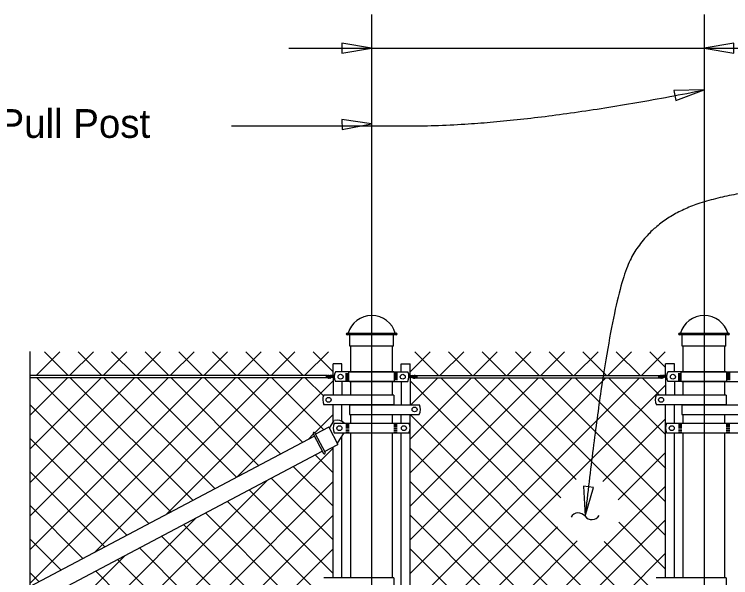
# Model space of a CAD drawing. Extents: x 0.5 to 39.7, y 0.9 to 25.6.
# Drawn here: x 23.73 to 28.76, y 21.55 to 25.5 of the extents above; entities that cross this region are included whole.
import ezdxf

# ---------------------------------------------------------------- set-up
doc = ezdxf.new("R2010")
doc.units = 0
for name, color, linetype in [('CL_Major', 7, 'Continuous'), ('Dimension', 7, 'Continuous'), ('Miscellaneous', 7, 'Continuous'), ('SteelMisc', 7, 'Continuous'), ('TextStructures', 7, 'Continuous')]:
    doc.layers.add(name, color=color, linetype=linetype)

msp = doc.modelspace()

# ---------------------------------------------------------------- linework, layer by layer
at = {"layer": 'CL_Major'}
for p, q in [((26.2429, 25.5043), (26.2429, 12.3953)), ((28.5763, 25.5043), (28.5763, 13.5039))]:
    msp.add_line(p, q, dxfattribs=at)
at = {"layer": 'Dimension'}
msp.add_line((25.6609, 25.2672), (34.1233, 25.2672), dxfattribs=at)
for points in [[(26.2429, 25.2672), (26.0347, 25.3025), (26.0347, 25.2319)], [(28.5762, 25.2672), (28.7845, 25.2319), (28.7845, 25.3025)], [(28.5762, 24.9738), (28.3651, 24.9702), (28.378, 24.9009)], [(26.2429, 24.737), (26.0337, 24.766), (26.0358, 24.6954)], [(27.7412, 21.9834), (27.8008, 22.186), (27.7307, 22.1943)]]:
    msp.add_lwpolyline(points, close=True, dxfattribs=at)
msp.add_lwpolyline([(23.8431, 23.1382), (23.8431, 21.1819), (23.9465, 21.1819), (23.8431, 21.1369), (23.7398, 21.0919), (23.8431, 21.0919), (23.8431, 20.1983)], dxfattribs=at)
for centre, start, end in [((27.6938, 21.9472), 37.4003, 149.1275), ((27.7886, 22.0196), 217.4003, 329.1275)]:
    msp.add_arc(centre, 0.0596, start, end, dxfattribs=at)
for points in [[(25.2588, 24.7214), (25.7125, 24.7214), (27.3088, 24.7214), (28.5763, 24.9737)], [(29.3712, 24.2725), (28.9427, 24.2977), (28.2117, 24.0791), (27.9092, 23.4903), (27.7412, 21.9834)]]:
    msp.add_open_spline(points, degree=2, dxfattribs=at)
at = {"layer": 'Miscellaneous'}
for p, q in [((24.0538, 23.1361), (23.8871, 22.9695)), ((24.113, 22.9695), (23.9463, 23.1361)), ((24.2895, 23.1361), (24.1228, 22.9695)), ((24.3487, 22.9695), (24.182, 23.1361)), ((24.5252, 23.1361), (24.3585, 22.9695)), ((24.5844, 22.9695), (24.4177, 23.1361)), ((24.7609, 23.1361), (24.5942, 22.9695)), ((24.8201, 22.9695), (24.6534, 23.1361)), ((24.9966, 23.1361), (24.8299, 22.9695)), ((25.0558, 22.9695), (24.8891, 23.1361)), ((25.2323, 23.1361), (25.0656, 22.9695)), ((25.2915, 22.9695), (25.1248, 23.1361)), ((25.468, 23.1361), (25.3013, 22.9695)), ((25.5272, 22.9695), (25.3605, 23.1361)), ((25.7037, 23.1361), (25.537, 22.9695)), ((25.7629, 22.9695), (25.5962, 23.1361)), ((25.9394, 23.1361), (25.7727, 22.9695)), ((25.972, 22.996), (25.8319, 23.1361)), ((26.5138, 22.996), (26.6539, 23.1361)), ((26.5465, 23.1361), (26.7131, 22.9695)), ((26.7229, 22.9695), (26.8896, 23.1361)), ((26.7822, 23.1361), (26.9488, 22.9695)), ((26.9586, 22.9695), (27.1253, 23.1361)), ((27.0179, 23.1361), (27.1845, 22.9695)), ((27.1943, 22.9695), (27.361, 23.1361)), ((27.2536, 23.1361), (27.4202, 22.9695)), ((27.4301, 22.9695), (27.5967, 23.1361)), ((27.4893, 23.1361), (27.6559, 22.9695)), ((27.6658, 22.9695), (27.8324, 23.1361)), ((27.725, 23.1361), (27.8916, 22.9695)), ((27.9015, 22.9695), (28.0681, 23.1361)), ((27.9607, 23.1361), (28.1273, 22.9695)), ((28.1372, 22.9695), (28.3038, 23.1361)), ((28.1964, 23.1361), (28.3054, 23.0271)), ((25.2865, 22.9547), (23.8431, 21.5113)), ((25.0508, 22.9547), (23.8431, 21.747)), ((24.8151, 22.9547), (23.8431, 21.9827)), ((24.5794, 22.9547), (23.8431, 22.2184)), ((24.3437, 22.9547), (23.8431, 22.4541)), ((24.108, 22.9547), (23.8431, 22.6898)), ((24.8328, 22.014), (23.892, 22.9547)), ((24.987, 22.0955), (24.1277, 22.9547)), ((25.5223, 22.9547), (24.3, 21.7324)), ((25.1412, 22.177), (24.3634, 22.9547)), ((25.2954, 22.2584), (24.5991, 22.9547)), ((25.758, 22.9547), (24.7998, 21.9966)), ((25.4496, 22.3399), (24.8348, 22.9547)), ((25.6038, 22.4214), (25.0705, 22.9547)), ((25.972, 22.9331), (25.2997, 22.2607)), ((25.758, 22.5029), (25.3062, 22.9547)), ((25.9072, 22.5894), (25.5419, 22.9547)), ((25.905, 22.8273), (25.7776, 22.9547)), ((26.5138, 22.2889), (27.1796, 22.9547)), ((26.5138, 21.5818), (27.8867, 22.9547)), ((26.5138, 21.8175), (27.651, 22.9547)), ((26.5138, 22.0532), (27.4153, 22.9547)), ((26.5138, 21.3461), (28.1224, 22.9547)), ((26.5138, 22.5246), (26.9439, 22.9547)), ((26.5138, 22.9331), (28.3054, 21.1415)), ((26.5188, 22.7654), (26.7082, 22.9547)), ((26.7279, 22.9547), (27.5705, 22.1121)), ((26.9636, 22.9547), (27.6781, 22.2402)), ((27.1993, 22.9547), (28.3054, 21.8486)), ((27.435, 22.9547), (28.3054, 22.0843)), ((27.6707, 22.9547), (28.308, 22.3174)), ((27.9064, 22.9547), (28.3054, 22.5557)), ((28.1421, 22.9547), (28.2638, 22.833)), ((26.5138, 21.1104), (28.3054, 22.902)), ((24.6785, 21.9325), (23.8447, 22.7664)), ((25.972, 22.6974), (25.8432, 22.5686)), ((26.5138, 22.6974), (28.3054, 20.9058)), ((27.8667, 22.2276), (28.3054, 22.6663)), ((24.5243, 21.851), (23.8431, 22.5322)), ((25.8333, 22.5587), (25.7995, 22.5249)), ((25.972, 22.4617), (23.8431, 20.3328)), ((26.5138, 22.4617), (28.3054, 20.6701)), ((27.9743, 22.0995), (28.3054, 22.4306)), ((25.972, 22.2889), (25.8468, 22.4142)), ((25.972, 22.0532), (25.6926, 22.3327)), ((24.3701, 21.7695), (23.8431, 22.2965)), ((25.5118, 22.2371), (23.8431, 20.5685)), ((25.972, 21.8175), (25.5384, 22.2512)), ((25.972, 22.226), (23.8431, 20.0971)), ((26.5138, 22.226), (28.3054, 20.4344)), ((26.5138, 20.4033), (28.3054, 22.1949)), ((25.972, 21.5818), (25.3841, 22.1697)), ((25.972, 21.3461), (25.2299, 22.0882)), ((24.2159, 21.688), (23.8431, 22.0608)), ((25.972, 21.9903), (23.8431, 19.8614)), ((25.9649, 21.1175), (25.0757, 22.0067)), ((26.5138, 21.9903), (28.2366, 20.2675)), ((25.012, 21.973), (23.8431, 20.8042)), ((25.972, 20.8747), (24.9215, 21.9252)), ((26.5505, 20.2043), (28.3054, 21.9592)), ((27.9776, 21.9407), (28.3054, 21.6129)), ((26.5138, 20.8747), (27.5488, 21.9097)), ((24.0617, 21.6065), (23.8431, 21.8251)), ((25.972, 20.639), (24.7673, 21.8437)), ((26.5138, 20.639), (27.685, 21.8102)), ((27.8761, 21.8065), (28.3054, 21.3772)), ((25.972, 21.7546), (23.8431, 19.6257)), ((25.972, 20.4033), (24.6131, 21.7622)), ((26.5138, 21.7546), (28.3054, 19.963)), ((26.5138, 19.9319), (28.3054, 21.7235)), ((24.5121, 21.7089), (23.8431, 21.0399)), ((25.8996, 20.24), (24.4589, 21.6807)), ((23.9075, 21.525), (23.8431, 21.5894)), ((25.972, 19.9319), (24.3047, 21.5992))]:
    msp.add_line(p, q, dxfattribs=at)
at = {"layer": 'SteelMisc'}
for p, q in [((26.0707, 23.2681), (26.4153, 23.2681)), ((26.4153, 23.2559), (26.0707, 23.2559)), ((26.0889, 23.1761), (26.0889, 23.2559)), ((26.397, 23.1761), (26.397, 23.2559)), ((28.404, 23.2681), (28.7486, 23.2681)), ((28.7486, 23.2559), (28.404, 23.2559)), ((28.4222, 23.1761), (28.4222, 23.2559)), ((28.7304, 23.1761), (28.7304, 23.2559)), ((26.397, 23.1761), (26.0889, 23.1761)), ((26.0971, 22.9966), (26.0971, 23.1761)), ((26.3888, 22.9966), (26.3888, 23.1761)), ((28.7304, 23.1761), (28.4222, 23.1761)), ((28.4305, 22.9966), (28.4305, 23.1761)), ((28.7221, 22.9966), (28.7221, 23.1761)), ((25.972, 22.9726), (25.972, 23.0528)), ((26.0345, 23.0528), (25.972, 23.0528)), ((26.0345, 22.9966), (26.0345, 23.0528)), ((26.4513, 22.9966), (26.4513, 23.0528)), ((26.4513, 23.0528), (26.5138, 23.0528)), ((26.4513, 22.9966), (26.4513, 23.0528)), ((26.4513, 23.0528), (26.5138, 23.0528)), ((26.5138, 22.9726), (26.5138, 23.0528)), ((26.5138, 22.9726), (26.5138, 23.0528)), ((28.3054, 22.9726), (28.3054, 23.0528)), ((28.3679, 23.0528), (28.3054, 23.0528)), ((28.3679, 22.9966), (28.3679, 23.0528)), ((26.3988, 22.9966), (25.989, 22.9966)), ((26.0604, 22.9858), (26.0834, 22.9858)), ((26.0834, 22.9289), (26.0834, 22.9966)), ((26.0872, 22.9966), (26.4969, 22.9966)), ((26.4254, 22.9858), (26.4024, 22.9858)), ((26.4026, 22.9289), (26.4026, 22.9966)), ((28.7321, 22.9966), (28.3223, 22.9966)), ((28.3937, 22.9858), (28.4167, 22.9858)), ((28.4167, 22.9289), (28.4167, 22.9966)), ((28.4206, 22.9966), (28.8303, 22.9966)), ((28.7588, 22.9858), (28.7358, 22.9858)), ((28.7359, 22.9289), (28.7359, 22.9966)), ((25.9337, 22.9695), (23.8431, 22.9695)), ((25.935, 22.9547), (23.8431, 22.9547)), ((25.9811, 22.9537), (25.9474, 22.9593)), ((25.9807, 22.9585), (25.9509, 22.9634)), ((25.9817, 22.9741), (25.9524, 22.9695)), ((25.981, 22.9691), (25.9549, 22.965)), ((25.972, 22.9676), (25.972, 22.9598)), ((25.972, 22.9552), (25.972, 22.833)), ((26.0604, 22.9802), (26.0834, 22.9802)), ((26.0604, 22.9722), (26.0834, 22.9722)), ((26.0604, 22.9667), (26.0834, 22.9667)), ((26.0604, 22.9587), (26.0834, 22.9587)), ((26.0604, 22.9531), (26.0834, 22.9531)), ((26.0604, 22.9451), (26.0834, 22.9451)), ((26.0604, 22.9396), (26.0834, 22.9396)), ((26.4254, 22.9802), (26.4024, 22.9802)), ((26.4254, 22.9722), (26.4024, 22.9722)), ((26.4254, 22.9667), (26.4024, 22.9667)), ((26.4254, 22.9587), (26.4024, 22.9587)), ((26.4254, 22.9531), (26.4024, 22.9531)), ((26.4254, 22.9451), (26.4024, 22.9451)), ((26.4254, 22.9396), (26.4024, 22.9396)), ((26.5042, 22.9741), (26.5335, 22.9695)), ((26.5043, 22.9741), (26.5336, 22.9695)), ((26.5047, 22.9537), (26.5384, 22.9593)), ((26.5048, 22.9691), (26.5309, 22.965)), ((26.5048, 22.9537), (26.5385, 22.9593)), ((26.5049, 22.9691), (26.531, 22.965)), ((26.5052, 22.9585), (26.5351, 22.9634)), ((26.5053, 22.9585), (26.5352, 22.9634)), ((26.5138, 22.9676), (26.5138, 22.9598)), ((26.5138, 22.9676), (26.5138, 22.9598)), ((26.5138, 22.9552), (26.5138, 22.7653)), ((26.5138, 22.9552), (26.5138, 22.7653)), ((26.5509, 22.9547), (28.2683, 22.9547)), ((26.5522, 22.9695), (28.267, 22.9695)), ((28.3144, 22.9537), (28.2808, 22.9593)), ((28.314, 22.9585), (28.2842, 22.9634)), ((28.3151, 22.9741), (28.2858, 22.9695)), ((28.3143, 22.9691), (28.2883, 22.965)), ((28.3054, 22.9676), (28.3054, 22.9598)), ((28.3054, 22.9552), (28.3054, 22.833)), ((28.3937, 22.9802), (28.4167, 22.9802)), ((28.3937, 22.9722), (28.4167, 22.9722)), ((28.3937, 22.9667), (28.4167, 22.9667)), ((28.3937, 22.9587), (28.4167, 22.9587)), ((28.3937, 22.9531), (28.4167, 22.9531)), ((28.3937, 22.9451), (28.4167, 22.9451)), ((28.3937, 22.9396), (28.4167, 22.9396)), ((28.7588, 22.9802), (28.7358, 22.9802)), ((28.7588, 22.9722), (28.7358, 22.9722)), ((28.7588, 22.9667), (28.7358, 22.9667)), ((28.7588, 22.9587), (28.7358, 22.9587)), ((28.7588, 22.9531), (28.7358, 22.9531)), ((28.7588, 22.9451), (28.7358, 22.9451)), ((28.7588, 22.9396), (28.7358, 22.9396)), ((26.3988, 22.9289), (25.9894, 22.9289)), ((26.0345, 22.9288), (26.0345, 22.833)), ((26.0872, 22.9289), (26.4966, 22.9289)), ((26.0971, 22.833), (26.0971, 22.9288)), ((26.3888, 22.833), (26.3888, 22.9288)), ((26.4513, 22.9288), (26.4513, 22.7653)), ((26.4513, 22.9288), (26.4513, 22.7653)), ((28.7321, 22.9289), (28.3228, 22.9289)), ((28.3679, 22.9288), (28.3679, 22.833)), ((28.4206, 22.9289), (28.8299, 22.9289)), ((28.4305, 22.833), (28.4305, 22.9288)), ((28.7221, 22.833), (28.7221, 22.9288)), ((26.3988, 22.833), (25.9077, 22.833)), ((26.3988, 22.833), (26.3988, 22.7654)), ((28.7321, 22.833), (28.241, 22.833)), ((28.7321, 22.833), (28.7321, 22.7654)), ((26.3988, 22.7654), (25.9084, 22.7654)), ((25.972, 22.641), (25.972, 22.7654)), ((26.0345, 22.6487), (26.0345, 22.7654)), ((26.0872, 22.7654), (26.0872, 22.6977)), ((26.0872, 22.7654), (26.5783, 22.7654)), ((28.7321, 22.7654), (28.2417, 22.7654)), ((28.3054, 21.5524), (28.3054, 22.7654)), ((28.3679, 22.6358), (28.3679, 22.7654)), ((28.4206, 22.7654), (28.4206, 22.6977)), ((28.4206, 22.7654), (28.9116, 22.7654)), ((26.0872, 22.6977), (26.5776, 22.6977)), ((26.0971, 22.6358), (26.0971, 22.6977)), ((26.3888, 22.6358), (26.3888, 22.6977)), ((26.4513, 22.6358), (26.4513, 22.6977)), ((26.5138, 21.4848), (26.5138, 22.6977)), ((28.4206, 22.6977), (28.9109, 22.6977)), ((28.4305, 22.6358), (28.4305, 22.6977)), ((28.7221, 22.6358), (28.7221, 22.6977)), ((25.9464, 22.6018), (25.9811, 22.6549)), ((25.9806, 22.6358), (26.5054, 22.6358)), ((28.3139, 22.6358), (28.8387, 22.6358)), ((25.9429, 22.6083), (25.8486, 22.5585)), ((25.9429, 22.6083), (26.0066, 22.4877)), ((26.0629, 22.628), (26.0864, 22.628)), ((26.0629, 22.6184), (26.0864, 22.6184)), ((26.0629, 22.6075), (26.0864, 22.6075)), ((26.0629, 22.5958), (26.0864, 22.5958)), ((26.0629, 22.584), (26.0864, 22.584)), ((26.423, 22.628), (26.3995, 22.628)), ((26.423, 22.6184), (26.3995, 22.6184)), ((26.423, 22.6075), (26.3995, 22.6075)), ((26.423, 22.5958), (26.3995, 22.5958)), ((26.423, 22.584), (26.3995, 22.584)), ((28.3962, 22.628), (28.4197, 22.628)), ((28.3962, 22.6184), (28.4197, 22.6184)), ((28.3962, 22.6075), (28.4197, 22.6075)), ((28.3962, 22.5958), (28.4197, 22.5958)), ((28.3962, 22.584), (28.4197, 22.584)), ((28.7563, 22.628), (28.7328, 22.628)), ((28.7563, 22.6184), (28.7328, 22.6184)), ((28.7563, 22.6075), (28.7328, 22.6075)), ((28.7563, 22.5958), (28.7328, 22.5958)), ((28.7563, 22.584), (28.7328, 22.584)), ((23.8431, 21.491), (25.8399, 22.5462)), ((25.8321, 22.5609), (25.9046, 22.4237)), ((25.844, 22.5671), (25.9165, 22.43)), ((25.9806, 22.568), (26.5054, 22.568)), ((26.0024, 22.4958), (26.0493, 22.5675)), ((26.0345, 21.5524), (26.0345, 22.5449)), ((26.0629, 22.5742), (26.0864, 22.5742)), ((26.0971, 21.5524), (26.0971, 22.568)), ((26.3888, 21.5524), (26.3888, 22.568)), ((26.423, 22.5742), (26.3995, 22.5742)), ((26.4513, 21.4848), (26.4513, 22.568)), ((28.3139, 22.568), (28.8387, 22.568)), ((28.3679, 21.5524), (28.3679, 22.568)), ((28.3962, 22.5742), (28.4197, 22.5742)), ((28.4305, 21.5524), (28.4305, 22.568)), ((28.7221, 21.5524), (28.7221, 22.568)), ((28.7563, 22.5742), (28.7328, 22.5742)), ((25.9123, 22.4379), (26.0066, 22.4877)), ((23.8431, 21.3553), (25.8959, 22.4401)), ((25.972, 21.5524), (25.972, 22.4695)), ((26.3988, 21.5524), (25.9077, 21.5524)), ((26.3988, 21.5524), (26.3988, 21.4848)), ((28.7321, 21.5524), (28.241, 21.5524)), ((28.7321, 21.5524), (28.7321, 21.4848))]:
    msp.add_line(p, q, dxfattribs=at)
for centre, radius, start, end in [((26.0708, 23.2618), 0.00613, 91.1647, 268.8353), ((26.4151, 23.2618), 0.00613, 271.1647, 88.8353), ((28.4041, 23.2618), 0.00613, 91.1647, 268.8353), ((28.7484, 23.2618), 0.00613, 271.1647, 88.8353), ((25.8382, 22.5639), 0.00673, 27.851, 207.851), ((25.9107, 22.4267), 0.00673, 207.851, 27.851)]:
    msp.add_arc(centre, radius, start, end, dxfattribs=at)
for centre, major_axis, ratio, start_param, end_param in [((26.2436, 23.227), (0.1711, 0), 0.957868, 0.252602, 2.888574), ((28.5769, 23.227), (0.1711, 0), 0.957868, 0.252602, 2.888574), ((26.0582, 22.963), (-0.0776, 0), 0.957868, 5.81433, 6.762456), ((26.4276, 22.963), (0.0776, 0), 0.957868, 5.803915, 6.752041), ((26.4276, 22.963), (0.0776, 0), 0.957868, 5.803915, 6.752041), ((28.3916, 22.963), (-0.0776, 0), 0.957868, 5.81433, 6.762456), ((25.9448, 22.9412), (-0.0274, 0), 0.957868, 5.133531, 5.654664), ((25.9368, 22.9562), (0.0142, 0), 0.957868, 1.486836, 3.141593), ((25.942, 22.9608), (-0.00944, 0), 0.957868, 6.009018, 8.249874), ((25.9415, 22.9617), (0.00872, 0), 0.957868, 1.29026, 2.959852), ((25.9415, 22.9617), (0.00503, 0), 0.92697, 1.570796, 4.502291), ((25.9481, 22.9612), (0.00872, 0), 0.957868, 1.29026, 4.182385), ((25.9538, 22.9604), (-0.0115, -0.0041), 0.737732, 4.35367, 7.47816), ((25.9525, 22.9588), (-0.00527, 0), 0.957868, 5.22362, 7.507542), ((25.9504, 22.9579), (-0.00301, 0), 0.957868, 6.141288, 6.278592), ((25.9557, 22.9555), (-0.00982, 0), 0.957868, 4.777514, 5.62749), ((25.9504, 22.9579), (-0.00301, 0), 0.957868, 1.11255, 2.999696), ((25.9497, 22.9601), (0.00453, 0), 0.957868, 0.731188, 1.133458), ((25.9498, 22.9596), (0.0095, 0), 0.957868, 5.011765, 6.030719), ((25.9498, 22.9596), (0.0095, 0), 0.957868, 0.230606, 0.609214), ((26.536, 22.9596), (-0.0095, 0), 0.957868, 5.673972, 6.052579), ((26.536, 22.9596), (-0.0095, 0), 0.957868, 5.673972, 6.052579), ((26.536, 22.9596), (-0.0095, 0), 0.957868, 0.252467, 1.271421), ((26.536, 22.9596), (-0.0095, 0), 0.957868, 0.252467, 1.271421), ((26.5302, 22.9555), (0.00982, 0), 0.957868, 0.655696, 1.505671), ((26.5302, 22.9555), (0.00982, 0), 0.957868, 0.655696, 1.505671), ((26.5321, 22.9604), (0.0115, -0.0041), 0.737732, 5.08821, 8.212701), ((26.5321, 22.9604), (0.0115, -0.0041), 0.737732, 5.08821, 8.212701), ((26.5355, 22.9579), (0.00301, 0), 0.957868, 3.28349, 5.170635), ((26.5355, 22.9579), (0.00301, 0), 0.957868, 3.28349, 5.170635), ((26.5361, 22.9601), (-0.00453, 0), 0.957868, 5.149727, 5.551998), ((26.5361, 22.9601), (-0.00453, 0), 0.957868, 5.149727, 5.551998), ((26.5333, 22.9588), (0.00527, 0), 0.957868, 5.058829, 7.342751), ((26.5333, 22.9588), (0.00527, 0), 0.957868, 5.058829, 7.342751), ((26.5377, 22.9612), (-0.00872, 0), 0.957868, 2.1008, 4.992926), ((26.5377, 22.9612), (-0.00872, 0), 0.957868, 2.1008, 4.992926), ((26.5355, 22.9579), (0.00301, 0), 0.957868, 0.004594, 0.141897), ((26.5355, 22.9579), (0.00301, 0), 0.957868, 0.004594, 0.141897), ((26.5439, 22.9608), (0.00944, 0), 0.957868, 4.316497, 6.557353), ((26.5439, 22.9608), (0.00944, 0), 0.957868, 4.316497, 6.557353), ((26.5443, 22.9617), (-0.00872, 0), 0.957868, 3.323334, 4.992926), ((26.5443, 22.9617), (-0.00872, 0), 0.957868, 3.323334, 4.992926), ((26.5443, 22.9617), (-0.00503, 0), 0.92697, 1.780895, 4.712389), ((26.5443, 22.9617), (-0.00503, 0), 0.92697, 1.780895, 4.712389), ((26.549, 22.9562), (-0.0142, 0), 0.957868, 3.141593, 4.79635), ((26.549, 22.9562), (-0.0142, 0), 0.957868, 3.141593, 4.79635), ((26.541, 22.9412), (0.0274, 0), 0.957868, 0.628521, 1.149654), ((26.541, 22.9412), (0.0274, 0), 0.957868, 0.628521, 1.149654), ((28.2701, 22.9562), (0.0142, 0), 0.957868, 1.486836, 3.141593), ((28.2781, 22.9412), (-0.0274, 0), 0.957868, 5.133531, 5.654664), ((28.2753, 22.9608), (-0.00944, 0), 0.957868, 6.009018, 8.249874), ((28.2749, 22.9617), (0.00872, 0), 0.957868, 1.29026, 2.959852), ((28.2749, 22.9617), (0.00503, 0), 0.92697, 1.570796, 4.502291), ((28.2814, 22.9612), (0.00872, 0), 0.957868, 1.29026, 4.182385), ((28.2871, 22.9604), (-0.0115, -0.0041), 0.737732, 4.35367, 7.47816), ((28.2858, 22.9588), (-0.00527, 0), 0.957868, 5.22362, 7.507542), ((28.2837, 22.9579), (-0.00301, 0), 0.957868, 6.141288, 6.278592), ((28.289, 22.9555), (-0.00982, 0), 0.957868, 4.777514, 5.62749), ((28.2837, 22.9579), (-0.00301, 0), 0.957868, 1.11255, 2.999696), ((28.283, 22.9601), (0.00453, 0), 0.957868, 0.731188, 1.133458), ((28.2831, 22.9596), (0.0095, 0), 0.957868, 5.011765, 6.030719), ((28.2831, 22.9596), (0.0095, 0), 0.957868, 0.230606, 0.609214), ((25.9771, 22.7998), (-0.0776, 0), 0.957868, 5.821213, 6.765127), ((28.3105, 22.7998), (-0.0776, 0), 0.957868, 5.821213, 6.765127), ((26.5087, 22.7322), (0.0776, 0), 0.957868, 5.801244, 6.745158), ((26.5087, 22.7322), (0.0776, 0), 0.957868, 5.801244, 6.745158), ((26.0497, 22.6016), (-0.0776, 0), 0.957868, 5.810211, 6.75616), ((25.9977, 22.5866), (0.0647, 0.0342), 0.957868, 0.271397, 1.331255), ((26.4362, 22.6016), (0.0776, 0), 0.957868, 5.810211, 6.75616), ((28.383, 22.6016), (-0.0776, 0), 0.957868, 5.810211, 6.75616)]:
    msp.add_ellipse(centre, major_axis=major_axis, ratio=ratio, start_param=start_param, end_param=end_param, dxfattribs=at)
for centre, major_axis in [((26.0249, 22.9621), (0.0178, 0)), ((26.4609, 22.9621), (-0.0178, 0)), ((26.4609, 22.9621), (-0.0178, 0)), ((28.3582, 22.9621), (0.0178, 0)), ((25.9412, 22.8002), (0.0177, 0)), ((28.2746, 22.8002), (0.0177, 0)), ((26.5446, 22.7326), (-0.0177, 0)), ((26.5446, 22.7326), (-0.0177, 0)), ((26.0164, 22.6012), (0.0178, 0)), ((26.4695, 22.6012), (-0.0178, 0)), ((28.3497, 22.6012), (0.0178, 0))]:
    msp.add_ellipse(centre, major_axis=major_axis, ratio=0.957868, dxfattribs=at)

# ---------------------------------------------------------------- texts
at = {"layer": 'TextStructures'}
msp.add_text('℄ Pull Post', height=0.2016, dxfattribs=at).set_placement((23.4401, 24.6377))

doc.saveas('drawing.dxf')
